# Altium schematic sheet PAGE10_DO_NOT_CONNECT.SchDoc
size 381 x 304 mm; SheetNumber: 11; SheetTotal: 28
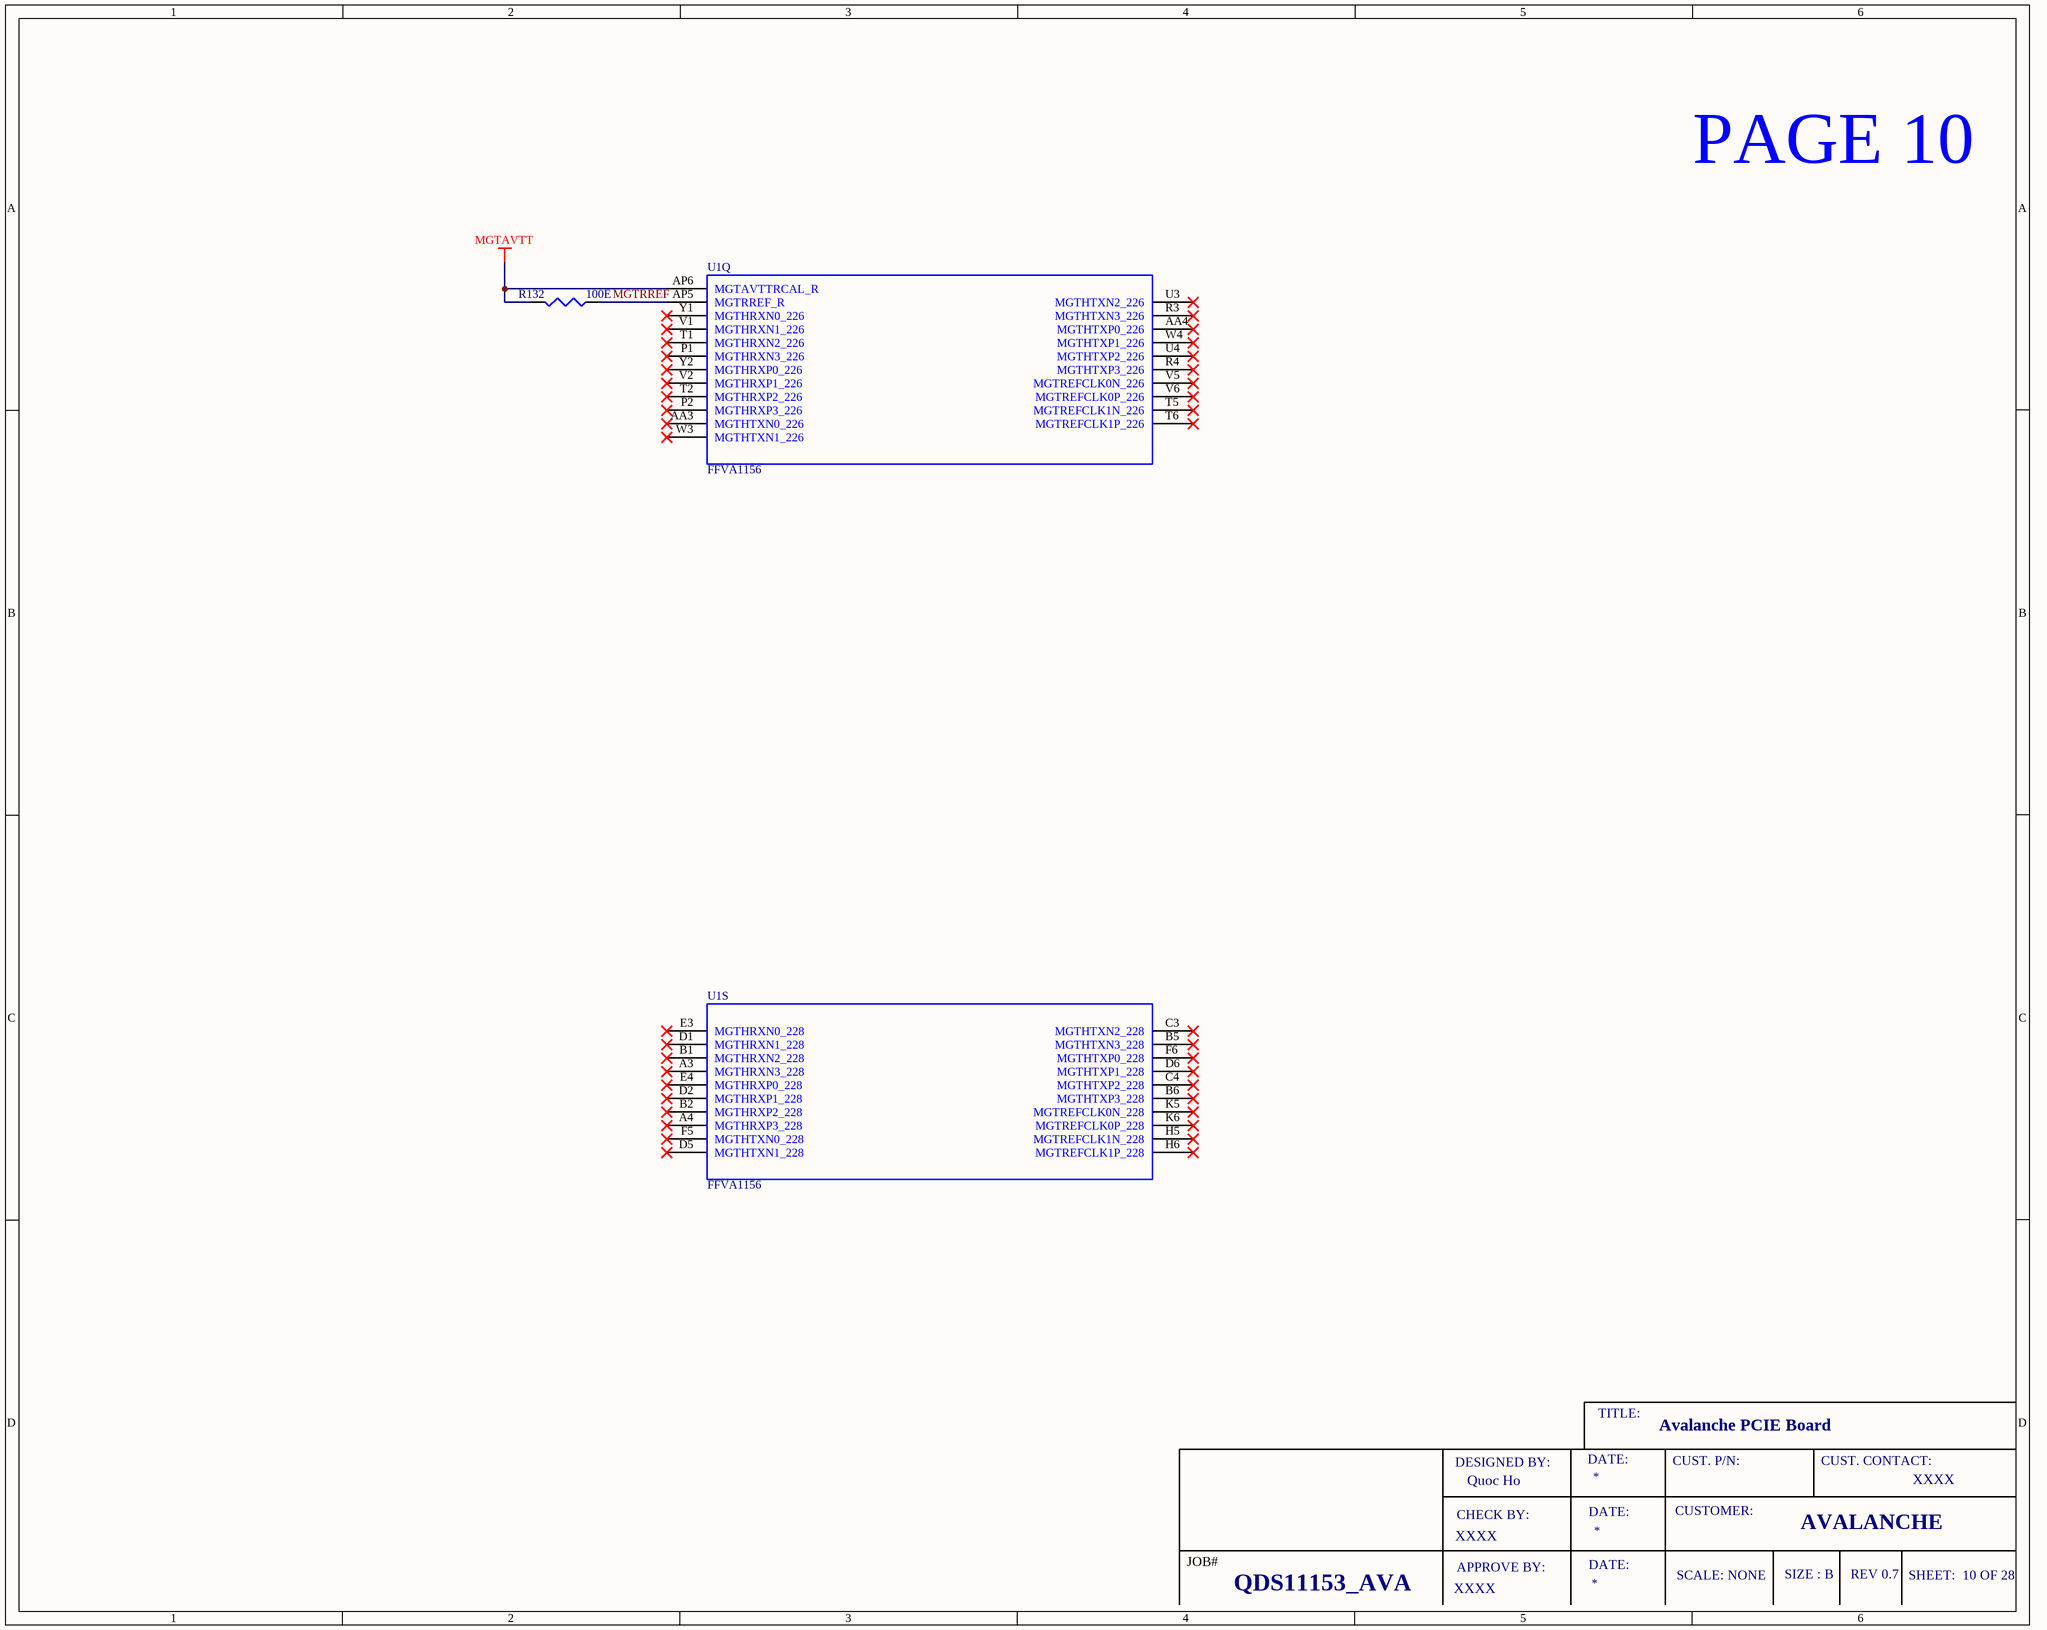
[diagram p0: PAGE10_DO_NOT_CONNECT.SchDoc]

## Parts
R132  100E  [RN_0402]
U1  FFVA1156  [FFVA1156]  (parts Q,S of 25)

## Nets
MGTAVTT: R132.2 U1.AP6(MGTAVTTRCAL_R)
MGTRREF: R132.1 U1.AP5(MGTRREF_R)

Not connected (* = marked no-connect by the designer): U1 A3(MGTHRXN3_228)* A4(MGTHRXP3_228)* AA3(MGTHTXN0_226)* AA4(MGTHTXP0_226)* B1(MGTHRXN2_228)* B2(MGTHRXP2_228)* B5(MGTHTXN3_228)* B6(MGTHTXP3_228)* C3(MGTHTXN2_228)* C4(MGTHTXP2_228)* D1(MGTHRXN1_228)* D2(MGTHRXP1_228)* D5(MGTHTXN1_228)* D6(MGTHTXP1_228)* E3(MGTHRXN0_228)* E4(MGTHRXP0_228)* F5(MGTHTXN0_228)* F6(MGTHTXP0_228)* H5(MGTREFCLK1N_228)* H6(MGTREFCLK1P_228)* K5(MGTREFCLK0N_228)* K6(MGTREFCLK0P_228)* P1(MGTHRXN3_226)* P2(MGTHRXP3_226)* R3(MGTHTXN3_226)* R4(MGTHTXP3_226)* T1(MGTHRXN2_226)* T2(MGTHRXP2_226)* T5(MGTREFCLK1N_226)* T6(MGTREFCLK1P_226)* U3(MGTHTXN2_226)* U4(MGTHTXP2_226)* V1(MGTHRXN1_226)* V2(MGTHRXP1_226)* V5(MGTREFCLK0N_226)* V6(MGTREFCLK0P_226)* W3(MGTHTXN1_226)* W4(MGTHTXP1_226)* Y1(MGTHRXN0_226)* Y2(MGTHRXP0_226)*

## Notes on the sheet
- PAGE 10
- TITLE:
- Avalanche PCIE Board
- DESIGNED BY:
- CHECK BY:
- Quoc Ho
- DATE:
- CUST. P/N:
- CUSTOMER:
- CUST. CONTACT:
- XXXX
- JOB#
- APPROVE BY:
- SCALE: NONE
- SIZE : B
- AVALANCHE
- REV 0.7
- SHEET:  10 OF 28
- QDS11153_AVA

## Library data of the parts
R132 = RES: RES 100 OHM 1% 1/16W 0402; Manufacturer: YAGEO; Manufacturer Part Number: RC0402FR-07100RL
U1 = FFVA1156: IC FPGA 516 I/O 1156FCBGA; Manufacturer Part Number: XCKU15P-1FFVA1156E; Manufacturer: AMD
